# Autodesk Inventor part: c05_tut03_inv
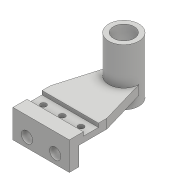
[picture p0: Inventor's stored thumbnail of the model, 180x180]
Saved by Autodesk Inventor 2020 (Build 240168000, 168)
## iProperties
Created: 2017-04
Part Number: c05_tut03_inv
Material: Generic
Document SubType Name: Modeling
Designer: CADCIM 00
Density: 1 g/cm^3
Appearance: Default
Author: CADCIM 00
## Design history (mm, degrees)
sketch "Sketch1"
  geometry: L1 (0, 0)-(-9, 0); L2 (-9, 0)-(-9, -4); L3 (-9, -4)-(-25, -4); L4 (-25, -4)-(-25, 0); L5 (-25, 0)-(-40, 0); L6 (-40, 0)-(-40, -30); L7 (-40, -30)-(-30, -30); L8 (-30, -30)-(-30, -10); L9 (-30, -10)-(0, -10); L10 (0, -10)-(0, 0)
  constraints: 20 end point, 7 perpendicular, 2 point on line, 1 horizontal, 1 vertical
  dimensions: "d0" = 4 distance of L1.end L2.end; "d1" = 16 distance of L2.end L3.end; "d3" = 15 distance of L4.end L5.end; "d4" = 30 distance of L5.end L6.end; "d5" = 10 distance of L6.end L7.end; "d6" = 10 distance of L9.end L1.start; "d7" = 40 distance between parallel lines of L10 L6
extrude "Extrusion1" new body sketch "Sketch1" stored distance "d8" = 60; taper "d9" = 0 deg
sketch "Sketch2"
  geometry: L1 (0, 9)-(60, 9) reference; L2 (0, 9)-(14, 57); L3 (14, 57)-(46, 57); L4 (46, 57)-(60, 9); L5 (60, 9)-(0, 9); L6 (30, 9)-(30, 57)
  constraints: 10 end point, 2 parallel, 1 midpoint, 1 vertical
  dimensions: "d10" = 48 distance between parallel lines of L3 L1; "d11" = 32 distance of L2.end L3.end
extrude "Extrusion2" join sketch "Sketch2" distance "d12" = 10; taper "d13" = 0 deg
workplane "Work Plane1"
sketch "Sketch3"
  geometry: L1 (46, 78)-(14, 78) reference; 2 further points
  constraints: 1 horizontal alignment, 1 midpoint, 2 other
extrude "Extrusion3" join sketch "Sketch3" distance "d15" = 60; taper "d16" = 0 deg
sketch "Sketch4"
  geometry: C1 r 11 at (0, 0); 1 further point
  constraints: 1 centre point
  dimensions: "d17" = 22 diameter of C1
extrude "Extrusion4" cut sketch "Sketch4" distance "d18" = 60; taper "d19" = 0 deg
sketch "Sketch5"
  geometry: L1 (0, 0)-(0, 16) reference; L2 (0, -15)-(60, -15) reference; C1 r 3 at (10, 7.5); C2 r 3 at (30, 7.5); C3 r 3 at (50, 7.5); 1 further point
  constraints: 3 centre point, 2 equal radius, 2 horizontal alignment
  dimensions: "d20" = 6 diameter of C1; "d21" = 10 distance from line of L1 C1.centre; "d22" = 20 distance of C1.centre C2.centre; "d24" = 22.5 distance from line of L2 C1.centre; "d33" = 20 distance of C3.centre C2.centre
extrude "Extrusion5" cut sketch "Sketch5" distance "d25" = 60; taper "d26" = 0 deg
sketch "Sketch6"
  geometry: L1 (0, 0)-(0, 30) reference; L2 (0, 0)-(60, 0) reference; C1 r 6 at (15, 10); C2 r 6 at (45, 10); 1 further point
  constraints: 2 centre point, 1 equal radius, 1 horizontal alignment
  dimensions: "d27" = 15 distance from line of L1 C1.centre; "d28" = 12 diameter of C1; "d29" = 30 distance of C2.centre C1.centre; "d30" = 10 distance from line of L2 C1.centre
extrude "Extrusion6" cut sketch "Sketch6" stored distance "d31" = 60; taper "d32" = 0 deg
body "Solid1"
